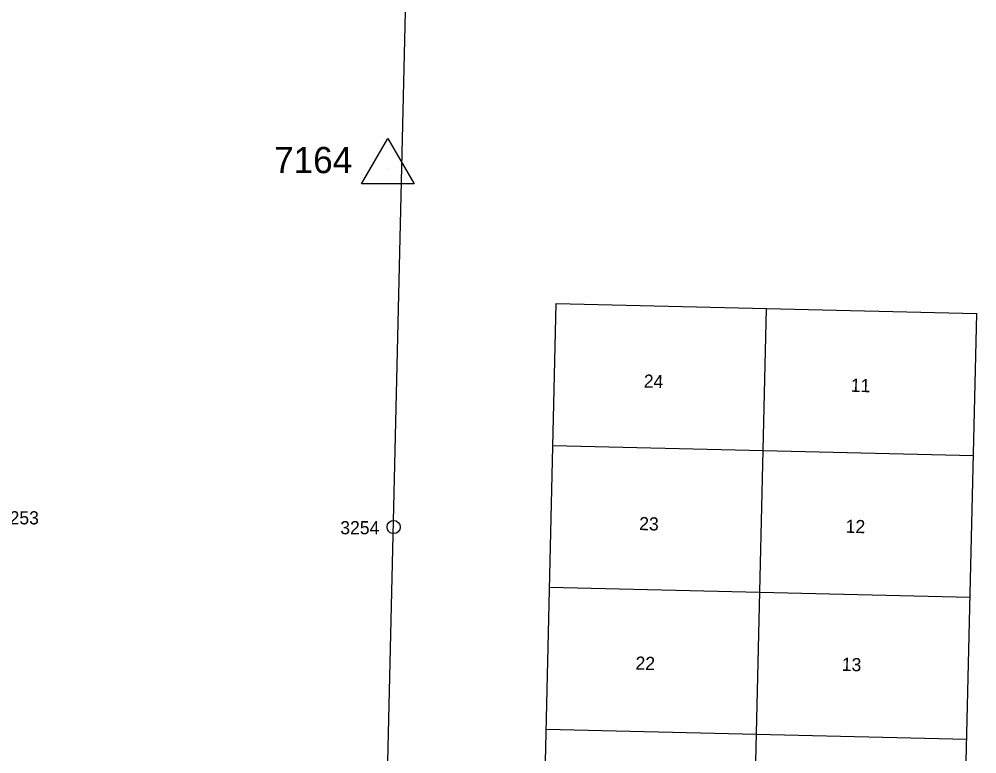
# Model space of a CAD drawing. Extents: x 7581380 to 7602708, y 543740 to 556109.
# Drawn here: x 7590482.1 to 7590846.4, y 550599.8 to 550879.3 of the extents above; entities that cross this region are included whole.
import ezdxf

# ---------------------------------------------------------------- set-up
doc = ezdxf.new("R2010")
doc.units = 0
for name, color, linetype in [('E_SURV_BNDRY_CROW', 7, 'Continuous'), ('E_SURV_BNDRY_Property', 7, 'Continuous'), ('E_SURV_BNDRY_SubdivisionTx', 7, 'Continuous'), ('E_SURV_MON_FdMon', 7, 'Continuous'), ('E_SURV_MON_FdMonTx', 7, 'Continuous'), ('E_SURV_NTW_SetNtwPt', 7, 'Continuous'), ('E_SURV_NTW_SetNtwPtTx', 7, 'Continuous')]:
    doc.layers.add(name, color=color, linetype=linetype)

msp = doc.modelspace()

# ---------------------------------------------------------------- linework, layer by layer
at = {"layer": 'E_SURV_BNDRY_CROW'}
for p, q in [((7590678.66, 550443.6), (7590686.39, 550771.12)), ((7590837.48, 550391.41), (7590846.36, 550767.35))]:
    msp.add_line(p, q, dxfattribs=at)
at = {"layer": 'E_SURV_BNDRY_Property'}
for p, q in [((7590613.52, 550215.07), (7590632.7, 551039.9)), ((7590686.38, 550771.12), (7590846.35, 550767.35)), ((7590757.31, 550385.34), (7590766.38, 550769.23)), ((7590685.11, 550717.13), (7590845.07, 550713.36)), ((7590683.84, 550663.15), (7590843.8, 550659.38)), ((7590682.56, 550609.16), (7590842.53, 550605.39))]:
    msp.add_line(p, q, dxfattribs=at)
at = {"layer": 'E_SURV_MON_FdMon'}
msp.add_circle((7590624.55, 550686.08), 2.5, dxfattribs=at)
at = {"layer": 'E_SURV_NTW_SetNtwPt'}
for p, q in [((7590612.34, 550816.63), (7590622.34, 550833.95)), ((7590622.34, 550833.95), (7590632.34, 550816.63)), ((7590622.34, 550822.41), (7590622.34, 550822.41)), ((7590632.34, 550816.63), (7590612.34, 550816.63))]:
    msp.add_line(p, q, dxfattribs=at)

# ---------------------------------------------------------------- texts
at = {"layer": 'E_SURV_BNDRY_SubdivisionTx'}
for s, p in [('24', (7590719.62, 550739.14)), ('11', (7590798.35, 550737.55)), ('23', (7590717.88, 550684.94)), ('12', (7590796.4, 550683.92)), ('22', (7590716.48, 550631.86)), ('13', (7590794.93, 550631.4))]:
    msp.add_text(s, height=5, rotation=358.4384, dxfattribs=at).set_placement(p)
at = {"layer": 'E_SURV_MON_FdMonTx'}
for s, p in [('3253', (7590474.77, 550687.1)), ('3254', (7590604.25, 550683.33))]:
    msp.add_text(s, height=5, dxfattribs=at).set_placement(p)
at = {"layer": 'E_SURV_NTW_SetNtwPtTx'}
msp.add_text('7164', height=10, dxfattribs=at).set_placement((7590579.07, 550820.7))

doc.saveas('drawing.dxf')
